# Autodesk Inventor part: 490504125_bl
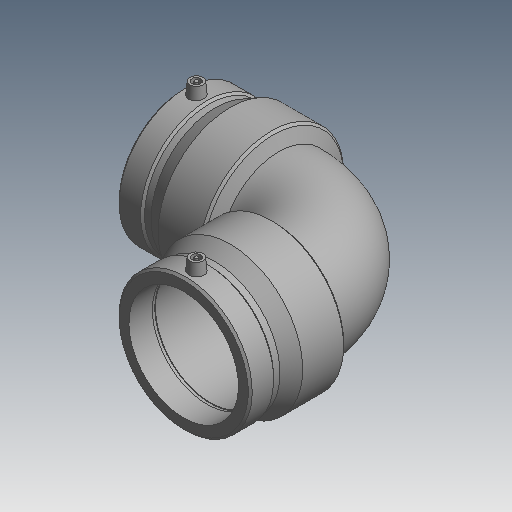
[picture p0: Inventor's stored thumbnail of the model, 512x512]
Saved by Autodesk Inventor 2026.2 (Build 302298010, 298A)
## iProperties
Created: 2017-06
Part Number: 490504125_bl
Material: Generic
Description: PLASSON 90° ELBOW 125
Document SubType Name: Modeling
Designer: KIM
Mass: 55.0731 g
Surface Area: 148.067 cm^2
Volume: 55.0731 cm^3
Density: 1 g/cm^3
Appearance: Default
Author: KIM
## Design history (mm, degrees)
derived "490504.ipt"
feature "Solid1::490504.ipt" dims "ScaleForDerivedMember" = 10
tag "TaggingFeature1"
body "Solid1"
other parameters: "d2" = 165 [user parameter], "d4" = 67.75 [user parameter], "d5" = 148.5 [user parameter], "d8" = 168 deg [user parameter], "d11" = 13.33333 [user parameter], "d14" = 17.6296 [user parameter], "d18" = 125 [user parameter], "d19" = 3.52592 [user parameter], "d20" = 168 deg [user parameter], "d22" = 151.8 [user parameter], "d23" = 165 [user parameter], "d24" = 147.246 [user parameter], "d29" = 89 [user parameter], "d30" = 15 [user parameter], "d31" = 94.85 [user parameter], "d34" = 5 deg [user parameter], "d35" = 15 [user parameter], "d39" = 5 deg [user parameter], "d41" = 4 [user parameter], "d42" = 14 [user parameter], "d43" = 0 [user parameter], "d45" = 4 [user parameter], "d46" = 14 [user parameter], "d47" = 0 [user parameter], "d49" = 125 [user parameter], "d50" = 106.25 [user parameter], "d54" = 90 deg [user parameter], "d65" = 125 [user parameter], "d67" = 45 deg [user parameter], "d71" = 90 deg [user parameter], "d75" = 8.25 [user parameter], "d82" = 45 deg [user parameter], "d84" = 148.5 [user parameter], "d87" = 90 deg [user parameter], "d91" = 0 [user parameter], "d93" = 0 [user parameter], "d94" = 90 deg [user parameter], "d101" = 3 [user parameter], "d102" = 0 [user parameter], "d103" = 3 [user parameter], "d104" = 0 [user parameter], "d105" = 29 [user parameter], "d106" = 7.25 [user parameter], "d110" = 55 [user parameter], "d111" = 271 [user parameter], "d112" = 271 [user parameter], "d113" = 271 [user parameter], "d114" = 271 [user parameter], "d_" = 125 [user parameter], "L_" = 271 [user parameter], "D_" = 165 [user parameter], "A_" = 89 [user parameter], "d_2" = 12 [user parameter]
